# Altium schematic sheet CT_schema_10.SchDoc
size 385 x 278 mm
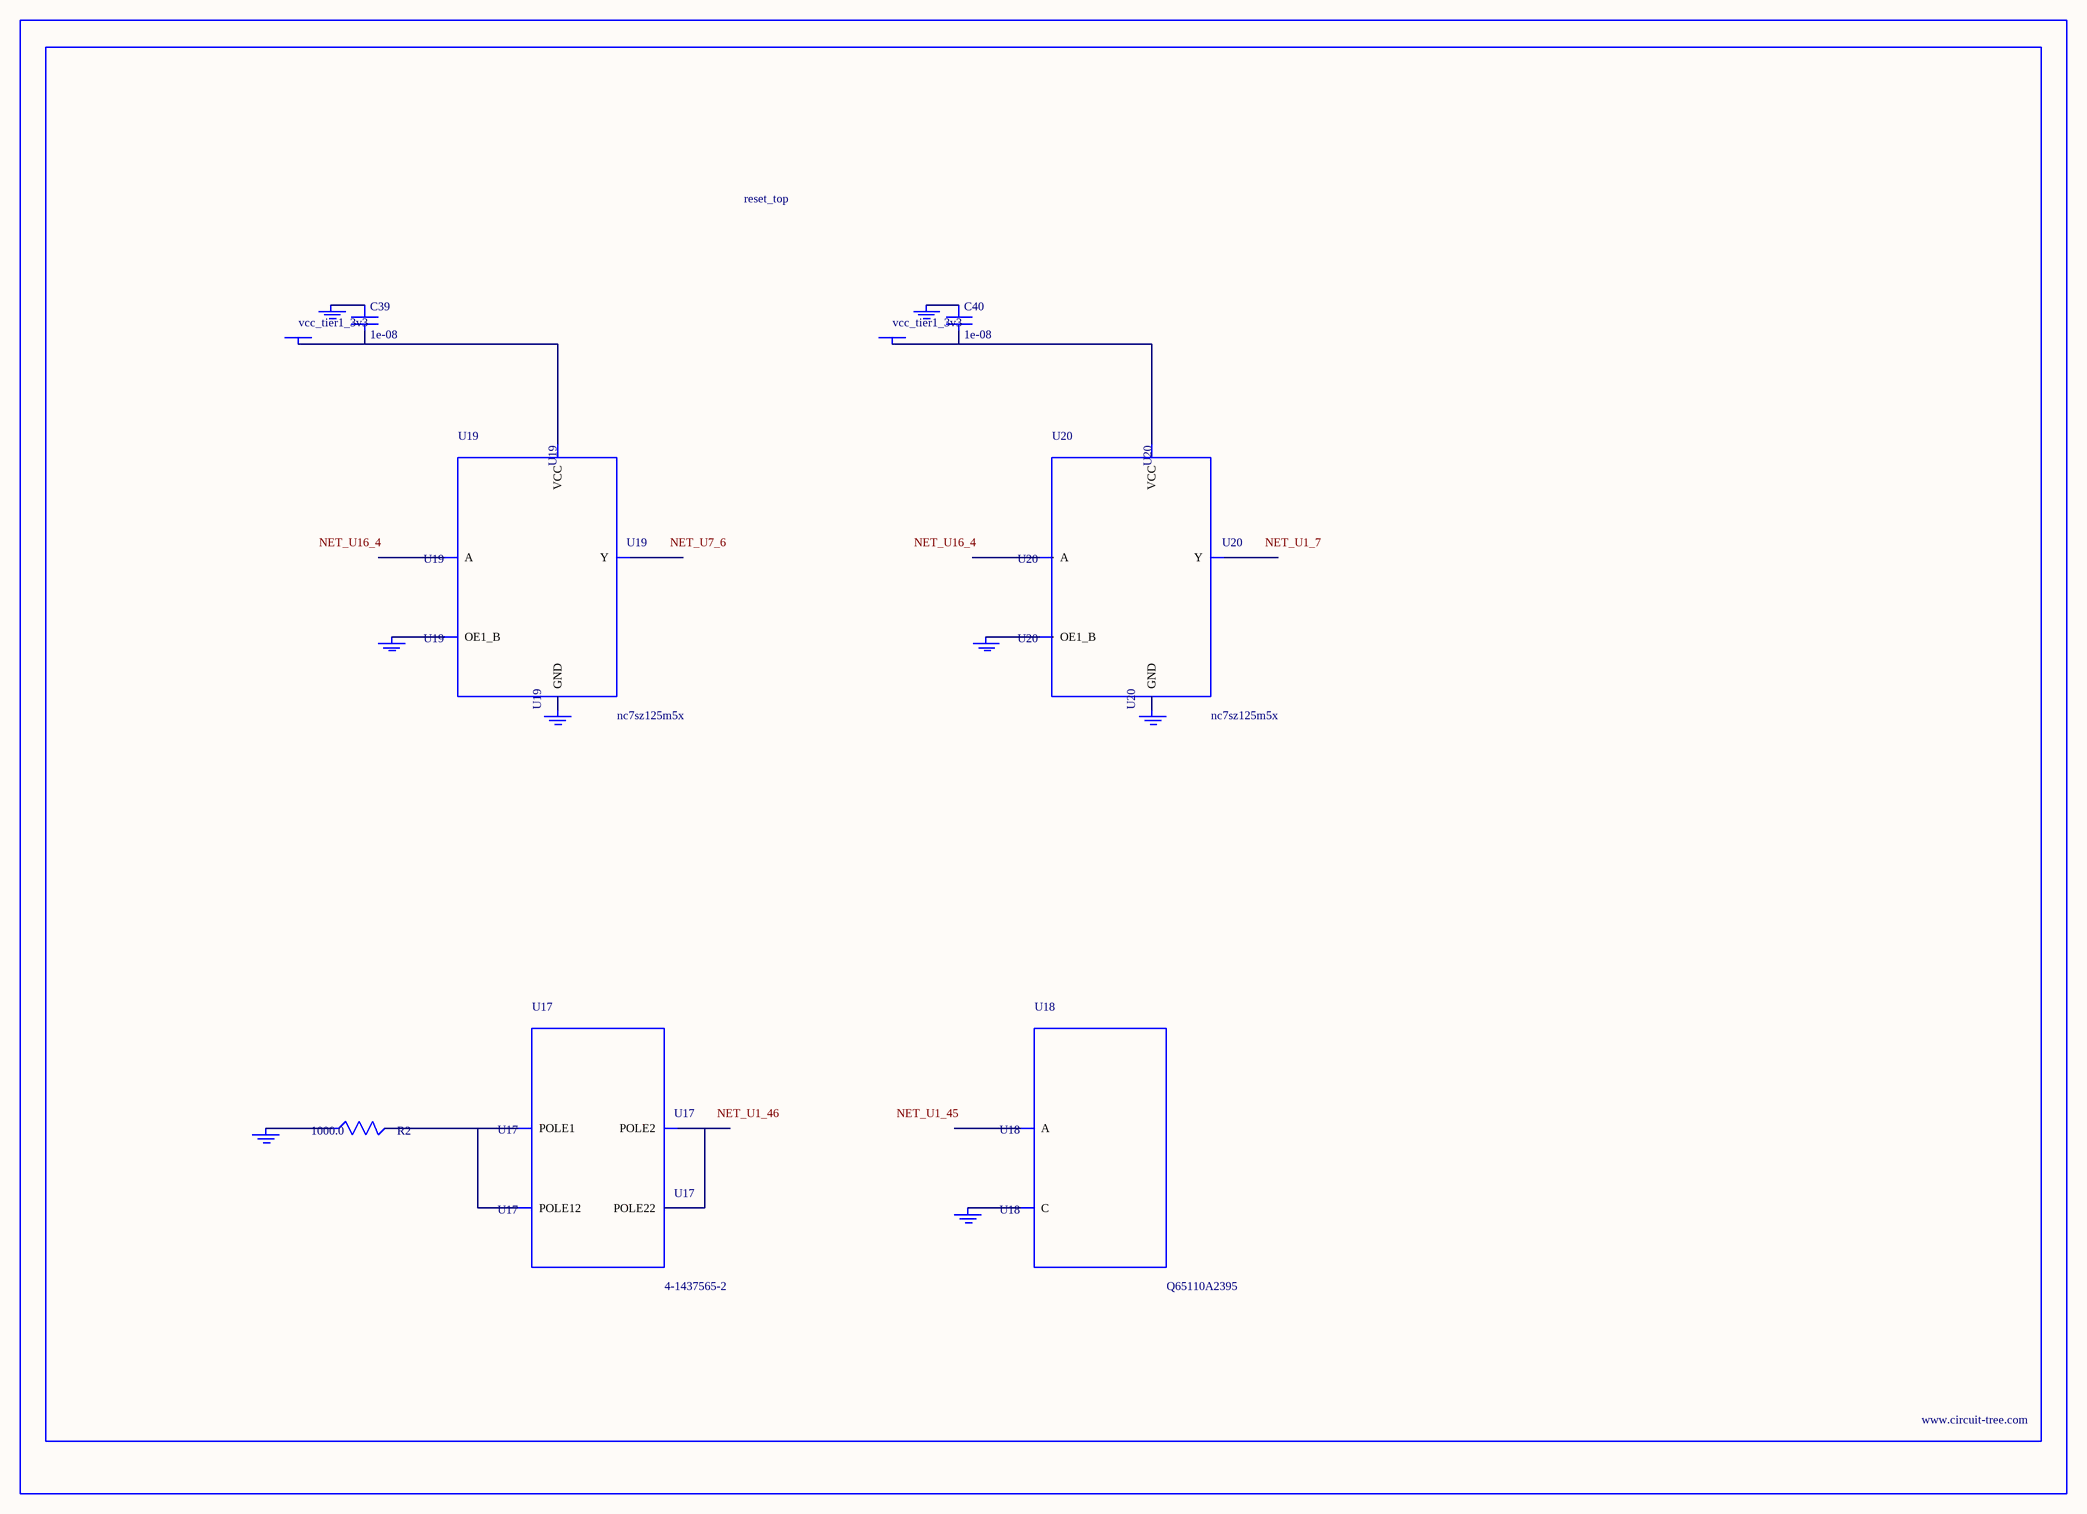
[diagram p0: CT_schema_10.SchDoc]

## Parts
BORDER9  (no value)
C39  1e-08  [C0402]
C40  1e-08  [C0402]
GND_INSTANCE_9_0  (no value)
GND_INSTANCE_9_1  (no value)
GND_INSTANCE_9_2  (no value)
GND_INSTANCE_9_3  (no value)
GND_INSTANCE_9_4  (no value)
GND_INSTANCE_9_5  (no value)
GND_INSTANCE_9_6  (no value)
GND_INSTANCE_9_7  (no value)
POWER_INSTANCE_9_0  vcc_tier1_3v3
POWER_INSTANCE_9_1  vcc_tier1_3v3
R2  1000.0  [R0603]
U17  4-1437565-2  [SW_4-1437565-2]
U18  Q65110A2395  [LGM67K-G1J2-24-Z]
U19  nc7sz125m5x  [NC7SZ125M5X]
U20  nc7sz125m5x  [NC7SZ125M5X]

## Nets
NetC39_1: C39.1 GND_INSTANCE_9_2.0(GND)
NetC39_2: C39.2 POWER_INSTANCE_9_0.0(PWR) U19.5(VCC)
NetC40_1: C40.1 GND_INSTANCE_9_5.0(GND)
NetC40_2: C40.2 POWER_INSTANCE_9_1.0(PWR) U20.5(VCC)
NetGND_INSTANCE_9_0_0: GND_INSTANCE_9_0.0(GND) R2.1
NetGND_INSTANCE_9_1_0: GND_INSTANCE_9_1.0(GND) U18.C
NetGND_INSTANCE_9_3_0: GND_INSTANCE_9_3.0(GND) U19.1(OE1_B)
NetGND_INSTANCE_9_4_0: GND_INSTANCE_9_4.0(GND) U19.3(GND)
NetGND_INSTANCE_9_6_0: GND_INSTANCE_9_6.0(GND) U20.1(OE1_B)
NetGND_INSTANCE_9_7_0: GND_INSTANCE_9_7.0(GND) U20.3(GND)
NetR2_2: R2.2 U17.1(POLE1) U17.2(POLE12)
NetU17_3: U17.3(POLE2) U17.4(POLE22)

Not connected (* = marked no-connect by the designer): U18 A; U19 2(A) 4(Y); U20 2(A) 4(Y)

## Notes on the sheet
- Labels drawn without touching a wire or pin: NET_U1_7, NET_U1_45, NET_U1_46, NET_U7_6, NET_U16_4

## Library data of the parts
BORDER9 = BORDER_PAGE9
C39 C40 = C0402C103K3RAC
GND_INSTANCE_9_0-GND_INSTANCE_9_7 = GND
POWER_INSTANCE_9_0 POWER_INSTANCE_9_1 = PWR
R2 = RC0603JR-071KL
